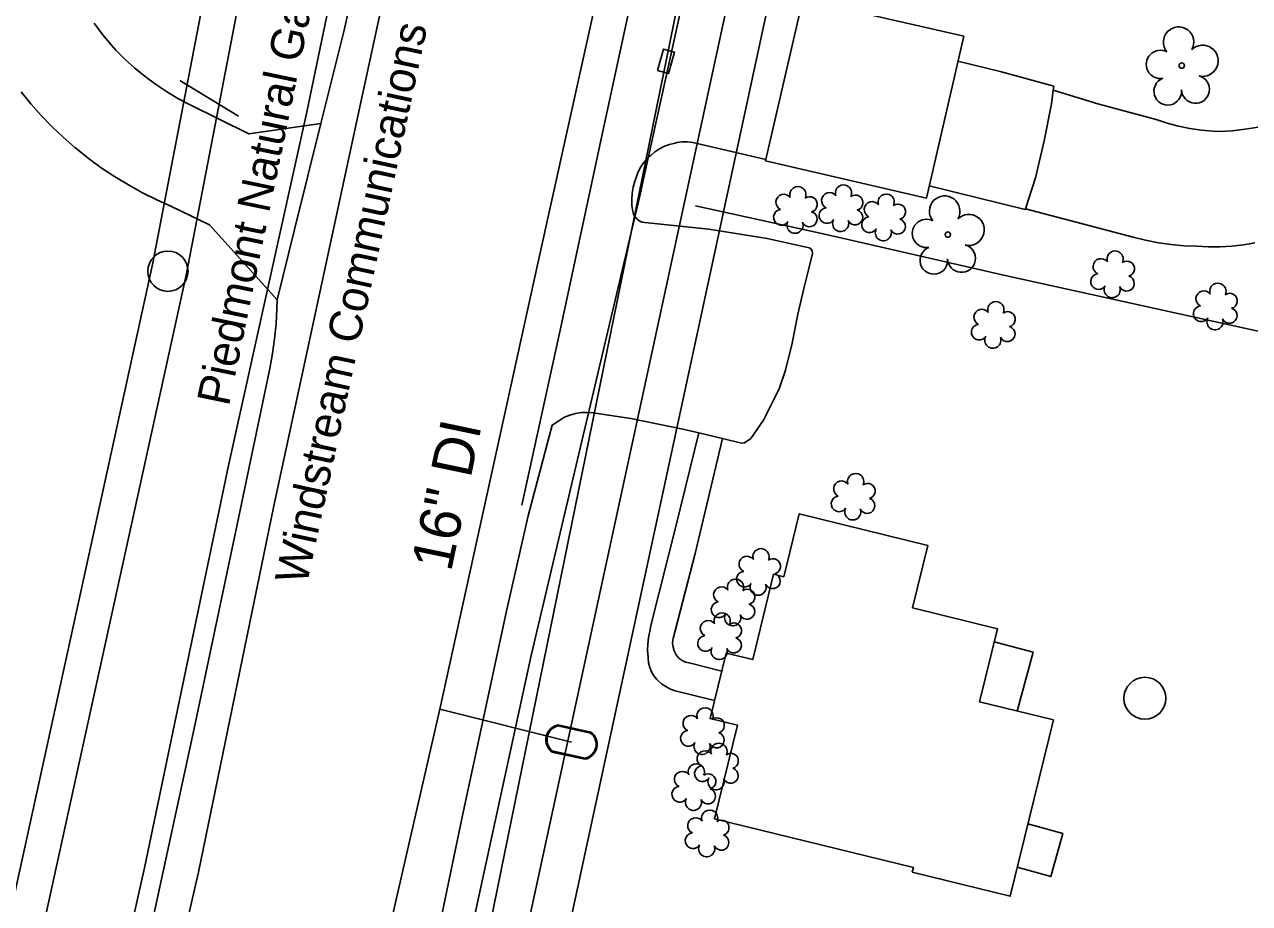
# Model space of a CAD drawing. Extents: x 1614427 to 1617186, y 896524 to 905462.
# Drawn here: x 1616442.5 to 1616592.1, y 900949.7 to 901056.9 of the extents above; entities that cross this region are included whole.
import ezdxf

# ---------------------------------------------------------------- set-up
doc = ezdxf.new("R2010")
doc.units = 0
for name, color, linetype in [('Exist Building', 7, 'Continuous'), ('Exist Building Metal Canopy', 7, 'Continuous'), ('Exist Other Culture Area Outline', 7, 'Continuous'), ('Exist Other Culture Fence Line', 7, 'Continuous'), ('Exist Other Culture Well CELL', 7, 'Continuous'), ('Exist Roads EOP', 7, 'Continuous'), ('Exist Roads EOP Other', 7, 'Continuous'), ('Exist Roads EOT', 7, 'Continuous'), ('Exist Roads Soil', 7, 'Continuous'), ('Exist Structure Minor Drop Inlet', 7, 'Continuous'), ('Exist Utilities Gas UG Line SUE LOS B', 7, 'Continuous'), ('Exist Utilities Gas UG Line SUE LOS B Text', 7, 'Continuous'), ('Exist Utilities Other Pole CELL', 7, 'Continuous'), ('Exist Utilities Power UG Cable SUE LOS D', 7, 'Continuous'), ('Exist Utilities Sanitary Sewer UG Line', 7, 'Continuous'), ('Exist Utilities Telephone UG Cable SUE LOS B', 7, 'Continuous'), ('Exist Utilities Telephone UG Cable SUE LOS B Text', 7, 'Continuous'), ('Exist Utilities Telephone UG FO SUE LOS B', 7, 'Continuous'), ('Exist Utilities Telephone UG FO SUE LOS D', 7, 'Continuous'), ('Exist Utilities TV UG FO Cable SUE LOS D', 7, 'Continuous'), ('Exist Utilities Water Meter CELL', 7, 'Continuous'), ('Exist Utilities Water UG Line SUE LOS B', 7, 'Continuous'), ('Exist Utilities Water UG Line SUE LOS B Text', 7, 'Continuous'), ('Exist Vegetation Shrub CELL', 7, 'Continuous'), ('Exist Vegetation Tree CELL', 7, 'Continuous')]:
    doc.layers.add(name, color=color, linetype=linetype)

msp = doc.modelspace()

# ---------------------------------------------------------------- linework, layer by layer
at = {"layer": 'Exist Building'}
msp.add_lwpolyline([(1616526.76, 900960), (1616529.56, 900971.41), (1616526.22, 900972.23), (1616528.18, 900980.22), (1616531.42, 900979.43), (1616533.97, 900989.83), (1616535.21, 900989.53), (1616537.09, 900997.21), (1616552.79, 900993.36), (1616550.93, 900985.74), (1616561.3, 900983.19), (1616559.11, 900974.28), (1616568.13, 900972.06), (1616562.85, 900950.53), (1616550.89, 900953.47), (1616551.04, 900954.05)], close=True, dxfattribs=at)
at = {"layer": 'Exist Building Metal Canopy'}
msp.add_lwpolyline([(1616537.54, 901060.03), (1616557.18, 901055.5), (1616552.62, 901035.75), (1616532.98, 901040.28)], close=True, dxfattribs=at)
at = {"layer": 'Exist Other Culture Area Outline'}
for points in [[(1616526.76, 900974.43), (1616521.96, 900975.59), (1616521.37, 900975.82), (1616520.81, 900976.12), (1616520.28, 900976.48), (1616519.81, 900976.91), (1616519.72, 900977), (1616519.36, 900977.45), (1616519.07, 900977.94), (1616518.85, 900978.47), (1616518.71, 900979.02), (1616518.64, 900979.59), (1616518.64, 900979.77), (1616518.59, 900980.54), (1616518.6, 900981.31), (1616518.69, 900982.08), (1616518.77, 900982.5), (1616519.03, 900983.73), (1616522.11, 900995.97), (1616524.83, 901007.08)], [(1616527.64, 900978.01), (1616523.65, 900979.01), (1616523.22, 900979.12), (1616522.81, 900979.32), (1616522.45, 900979.57), (1616522.14, 900979.89), (1616522.01, 900980.07), (1616521.81, 900980.48), (1616521.69, 900980.92), (1616521.64, 900981.37), (1616521.68, 900981.82), (1616521.71, 900982), (1616524.37, 900992.38), (1616527.71, 901006.4)], [(1616560.9, 900981.6), (1616565.64, 900980.34), (1616563.72, 900973.14)], [(1616565.02, 900959.39), (1616569.27, 900958.21), (1616567.8, 900952.94), (1616563.72, 900954.08)]]:
    msp.add_lwpolyline(points, dxfattribs=at)
at = {"layer": 'Exist Other Culture Fence Line'}
msp.add_line((1616468.64, 901045.76), (1616461.46, 901050.08), dxfattribs=at)
msp.add_lwpolyline([(1616524.45, 901034.81), (1616540.38, 901031.29), (1616562.24, 901026.28), (1616602, 901017.55)], dxfattribs=at)
at = {"layer": 'Exist Other Culture Well CELL'}
msp.add_circle((1616579.29, 900974.7), 2.56, dxfattribs=at)
at = {"layer": 'Exist Roads EOP'}
for points in [[(1616457.99, 900946.8), (1616463.22, 900971), (1616468.64, 900996.67), (1616472.45, 901014.95), (1616472.78, 901016.76), (1616473.04, 901018.57), (1616473.22, 901020.39), (1616473.33, 901022.22), (1616473.35, 901023.31), (1616475.46, 901031.92), (1616478.7, 901044.85), (1616481.54, 901056.24), (1616487.87, 901084.85), (1616490.93, 901101.42), (1616493.73, 901118.12), (1616494.93, 901124.61), (1616496.65, 901132.78), (1616498.63, 901140.3)], [(1616506.95, 901008.01), (1616504.02, 900996.97), (1616501.39, 900985.55), (1616496, 900960.38), (1616490.77, 900935.39), (1616486.24, 900914.29), (1616481.23, 900890.84), (1616476.26, 900867), (1616470.04, 900838.9), (1616463.48, 900807.17), (1616456.7, 900775.38), (1616450.29, 900746.19), (1616449.34, 900741.63)]]:
    msp.add_lwpolyline(points, dxfattribs=at)
at = {"layer": 'Exist Roads EOP Other'}
for points in [[(1616478.7, 901044.85), (1616469.88, 901043.58), (1616462.64, 901047.16), (1616461.23, 901047.91), (1616459.85, 901048.74), (1616458.52, 901049.63), (1616457.23, 901050.58), (1616455.99, 901051.6), (1616454.8, 901052.67), (1616453.66, 901053.81), (1616453.13, 901054.39), (1616452.05, 901055.71), (1616451.03, 901057.08)], [(1616556.47, 901052.46), (1616561.61, 901051.19), (1616568.16, 901049.41), (1616568.11, 901048.91), (1616567.91, 901047.25), (1616567, 901042.72), (1616565.94, 901038.21), (1616564.72, 901034.45), (1616564.68, 901034.35), (1616552.96, 901037.22)], [(1616473.35, 901023.31), (1616465.08, 901032.48), (1616460.44, 901034.71), (1616458.65, 901035.52), (1616456.9, 901036.4), (1616455.19, 901037.35), (1616453.51, 901038.37), (1616451.88, 901039.45), (1616450.3, 901040.61), (1616448.76, 901041.82), (1616448.64, 901041.92), (1616447.22, 901043.17), (1616445.85, 901044.47), (1616444.54, 901045.83), (1616443.29, 901047.25), (1616442.1, 901048.71)], [(1616506.95, 901008.01), (1616508.43, 901009), (1616509.1, 901009.26), (1616509.79, 901009.45), (1616510.5, 901009.56), (1616511.22, 901009.59), (1616511.94, 901009.55), (1616512.18, 901009.51), (1616516.54, 901008.85), (1616522.88, 901007.54), (1616524.83, 901007.08), (1616527.71, 901006.4), (1616530.05, 901005.85), (1616530.4, 901005.89), (1616531.18, 901006.41), (1616532.72, 901008.66), (1616534.66, 901012.45), (1616535.42, 901014.74), (1616536.23, 901018.05), (1616536.94, 901021.58), (1616537.7, 901024.89), (1616538.3, 901027.33), (1616538.71, 901029), (1616538.67, 901029.31), (1616538.48, 901029.58), (1616538.29, 901029.67), (1616533.17, 901030.8), (1616526.06, 901031.97), (1616518.23, 901032.75), (1616517.88, 901032.82), (1616517.55, 901032.98), (1616517.27, 901033.2), (1616517.03, 901033.48), (1616516.86, 901033.8), (1616516.78, 901034.09), (1616516.67, 901034.83), (1616516.64, 901035.59), (1616516.69, 901036.34), (1616516.81, 901037.08), (1616517.02, 901037.8), (1616517.15, 901038.14), (1616517.35, 901038.76), (1616517.63, 901039.35), (1616517.97, 901039.9), (1616518.39, 901040.4), (1616518.86, 901040.85), (1616518.96, 901040.94), (1616519.48, 901041.38), (1616520.03, 901041.76), (1616520.64, 901042.07), (1616521.27, 901042.3), (1616521.93, 901042.46), (1616522.17, 901042.51), (1616522.82, 901042.59), (1616523.47, 901042.6), (1616524.12, 901042.52), (1616524.65, 901042.4), (1616533.02, 901040.47)]]:
    msp.add_lwpolyline(points, dxfattribs=at)
at = {"layer": 'Exist Roads EOT'}
msp.add_lwpolyline([(1616503.24, 900998.28), (1616507.89, 901019.64), (1616512.97, 901043.12), (1616518.77, 901070.05)], dxfattribs=at)
at = {"layer": 'Exist Roads Soil'}
for points in [[(1616568.11, 901048.91), (1616573.54, 901047.25), (1616580.66, 901045.32), (1616582.01, 901044.89), (1616583.39, 901044.53), (1616584.78, 901044.24), (1616586.19, 901044.04), (1616587.61, 901043.91), (1616588.34, 901043.88), (1616589.94, 901043.97), (1616591.53, 901044.14), (1616593.12, 901044.4)], [(1616592.72, 901030.28), (1616591.32, 901030.04), (1616589.91, 901029.88), (1616588.49, 901029.79), (1616587.07, 901029.79), (1616585.67, 901029.86), (1616584.09, 901029.92), (1616582.51, 901030.06), (1616580.95, 901030.29), (1616579.39, 901030.59), (1616577.85, 901030.97), (1616564.72, 901034.45)]]:
    msp.add_lwpolyline(points, dxfattribs=at)
at = {"layer": 'Exist Structure Minor Drop Inlet'}
msp.add_lwpolyline([(1616519.8, 901051.31), (1616520.52, 901053.92), (1616521.85, 901053.55), (1616521.13, 901050.94)], close=True, dxfattribs=at)
at = {"layer": 'Exist Utilities Gas UG Line SUE LOS B'}
msp.add_lwpolyline([(1616533.94, 901312.88), (1616530.75, 901298.82), (1616520.32, 901250.36), (1616511.78, 901206.52), (1616502.64, 901165.78), (1616495.45, 901133.17), (1616487.34, 901096.12), (1616476.93, 901046.05), (1616467.42, 901003.11), (1616457.16, 900954), (1616446.5, 900906.58)], dxfattribs=at)
at = {"layer": 'Exist Utilities Other Pole CELL'}
msp.add_circle((1616460.02, 901026.82), 2.46, dxfattribs=at)
at = {"layer": 'Exist Utilities Power UG Cable SUE LOS D'}
msp.add_lwpolyline([(1616472.94, 900803.7), (1616497.54, 900917.27), (1616543.86, 901131.07), (1616567.27, 901236.77), (1616608.79, 901427.38), (1616667.35, 901702.61)], dxfattribs=at)
at = {"layer": 'Exist Utilities Sanitary Sewer UG Line'}
msp.add_lwpolyline([(1616444.8, 900682.93), (1616490.78, 900905.02), (1616557.11, 901230.35), (1616512.18, 901240.77), (1616568.35, 901492.88)], dxfattribs=at)
at = {"layer": 'Exist Utilities Telephone UG Cable SUE LOS B'}
msp.add_lwpolyline([(1616503.04, 901208.05), (1616504.34, 901207.7), (1616513.47, 901204.29), (1616516.02, 901201.09), (1616509.49, 901166.04), (1616502.86, 901137.25), (1616493.6, 901093.66), (1616483.21, 901045.76), (1616472.94, 900998.19), (1616463.74, 900953.48), (1616452.75, 900905.89), (1616441.22, 900852.26), (1616431.02, 900805.67), (1616418.45, 900757.41), (1616403.67, 900741.28), (1616397.61, 900729.94), (1616386.99, 900684.21), (1616386.12, 900682.91)], dxfattribs=at)
at = {"layer": 'Exist Utilities Telephone UG FO SUE LOS B'}
msp.add_lwpolyline([(1616573.32, 901304.19), (1616571.87, 901297.63), (1616562.34, 901250.69), (1616562.09, 901228.25), (1616558.13, 901219.09), (1616545.13, 901168.85), (1616535.79, 901125.09), (1616527.27, 901079.83), (1616517.65, 901036.02), (1616504.35, 900979.92), (1616494.25, 900933.3)], dxfattribs=at)
at = {"layer": 'Exist Utilities Telephone UG FO SUE LOS D'}
msp.add_lwpolyline([(1616266.21, 900145.33), (1616308.81, 900340.55), (1616349.93, 900531.55), (1616382.65, 900683.55), (1616415.98, 900835.43), (1616458.15, 901027.62), (1616484.99, 901167.15), (1616540.12, 901401.87)], dxfattribs=at)
at = {"layer": 'Exist Utilities TV UG FO Cable SUE LOS D'}
for points in [[(1616152.19, 899610.51), (1616181.4, 899742.23), (1616224.51, 899936.62), (1616270.68, 900144.79), (1616313.06, 900339.79), (1616354.51, 900530.51), (1616387.28, 900682.32), (1616420.05, 900834.14), (1616462.24, 901026.32), (1616489.27, 901166.41), (1616544.61, 901400.99), (1616575.34, 901543.24), (1616671.95, 901701.27)], [(1616351.28, 900220.72), (1616414.71, 900507.45), (1616449.63, 900671.08), (1616477.75, 900802.82), (1616502.4, 900916.25), (1616548.57, 901130.04)]]:
    msp.add_lwpolyline(points, dxfattribs=at)
at = {"layer": 'Exist Utilities Water Meter CELL'}
msp.add_line((1616509.29, 900969.36), (1616509.29, 900969.36), dxfattribs=at)
for points in [[(1616507.64, 900971.32), (1616511.62, 900970.44)], [(1616507.67, 900971.46), (1616511.65, 900970.58)], [(1616510.92, 900967.26), (1616506.91, 900968.14)], [(1616510.95, 900967.39), (1616506.94, 900968.28)]]:
    msp.add_lwpolyline(points, dxfattribs=at)
for centre, radius, start, end in [((1616508.02, 900969.63), 1.86, 100.7257, 233.5271), ((1616508.03, 900969.63), 1.73, 102.8486, 231.33), ((1616510.56, 900969.08), 1.86, 281.196, 53.8561), ((1616510.57, 900969.08), 1.73, 282.6749, 52.4205)]:
    msp.add_arc(centre, radius, start, end, dxfattribs=at)
at = {"layer": 'Exist Utilities Water UG Line SUE LOS B'}
msp.add_line((1616493.22, 900973.35), (1616509.29, 900969.36), dxfattribs=at)
msp.add_lwpolyline([(1616565.13, 901306), (1616558.38, 901275.38), (1616550.46, 901237.52), (1616546.09, 901216.65), (1616544.67, 901209.59), (1616533.76, 901160.14), (1616524.79, 901115.98), (1616518.64, 901086.8), (1616514.38, 901069.28), (1616505.14, 901027.6), (1616493.22, 900973.35), (1616487.23, 900947.29)], dxfattribs=at)
at = {"layer": 'Exist Vegetation Shrub CELL'}
for p, q in [((1616536.71, 901034.11), (1616536.71, 901034.11)), ((1616542.28, 901034.32), (1616542.28, 901034.32)), ((1616547.49, 901033.21), (1616547.49, 901033.21)), ((1616575.43, 901026.25), (1616575.43, 901026.25)), ((1616587.98, 901022.33), (1616587.98, 901022.33)), ((1616560.87, 901020.09), (1616560.87, 901020.09)), ((1616543.75, 900999.12), (1616543.75, 900999.12)), ((1616532.2, 900989.94), (1616532.2, 900989.94)), ((1616529.1, 900986.21), (1616529.1, 900986.21)), ((1616527.46, 900982.09), (1616527.46, 900982.09)), ((1616525.36, 900970.52), (1616525.36, 900970.52)), ((1616527.07, 900966.19), (1616527.07, 900966.19)), ((1616524.3, 900963.68), (1616524.3, 900963.68)), ((1616525.93, 900958.03), (1616525.93, 900958.03))]:
    msp.add_line(p, q, dxfattribs=at)
for centre, radius, start, end in [((1616536.93, 901036.15), 0.99, 334.8391, 200.4717), ((1616540.79, 901035.45), 0.968, 35.8908, 245.4216), ((1616542.5, 901036.36), 0.99, 334.8391, 200.4717), ((1616535.22, 901035.24), 0.968, 35.8908, 245.4216), ((1616538.38, 901034.98), 0.929, 284.4567, 126.0861), ((1616543.95, 901035.19), 0.929, 284.4567, 126.0861), ((1616546, 901034.34), 0.968, 35.8908, 245.4216), ((1616547.71, 901035.25), 0.99, 334.8391, 200.4717), ((1616549.16, 901034.08), 0.929, 284.4567, 126.0861), ((1616534.91, 901033.4), 0.955, 95.1099, 327.9534), ((1616538.34, 901033.18), 0.937, 204.9913, 73.4601), ((1616540.48, 901033.62), 0.955, 95.1099, 327.9534), ((1616543.91, 901033.4), 0.937, 204.9913, 73.4601), ((1616545.68, 901032.5), 0.955, 95.1099, 327.9534), ((1616536.58, 901032.43), 0.984, 151.2797, 21.387), ((1616542.15, 901032.64), 0.984, 151.2797, 21.387), ((1616547.36, 901031.52), 0.984, 151.2797, 21.387), ((1616549.12, 901032.28), 0.937, 204.9913, 73.4601), ((1616575.66, 901028.3), 0.99, 334.8391, 200.4717), ((1616573.94, 901027.38), 0.968, 35.8908, 245.4216), ((1616577.1, 901027.12), 0.929, 284.4567, 126.0861), ((1616573.63, 901025.55), 0.955, 95.1099, 327.9534), ((1616577.06, 901025.33), 0.937, 204.9913, 73.4601), ((1616575.3, 901024.57), 0.984, 151.2797, 21.387), ((1616586.5, 901023.46), 0.968, 35.8908, 245.4216), ((1616588.21, 901024.37), 0.99, 334.8391, 200.4717), ((1616561.1, 901022.13), 0.99, 334.8391, 200.4717), ((1616589.65, 901023.2), 0.929, 284.4567, 126.0861), ((1616559.39, 901021.21), 0.968, 35.8908, 245.4216), ((1616562.55, 901020.96), 0.929, 284.4567, 126.0861), ((1616586.18, 901021.63), 0.955, 95.1099, 327.9534), ((1616589.62, 901021.4), 0.937, 204.9913, 73.4601), ((1616559.07, 901019.38), 0.955, 95.1099, 327.9534), ((1616562.51, 901019.16), 0.937, 204.9913, 73.4601), ((1616587.85, 901020.65), 0.984, 151.2797, 21.387), ((1616560.74, 901018.4), 0.984, 151.2797, 21.387), ((1616543.98, 901001.16), 0.99, 334.8391, 200.4717), ((1616542.27, 901000.25), 0.968, 35.8908, 245.4216), ((1616545.43, 900999.99), 0.929, 284.4567, 126.0861), ((1616541.95, 900998.42), 0.955, 95.1099, 327.9534), ((1616545.39, 900998.19), 0.937, 204.9913, 73.4601), ((1616543.63, 900997.44), 0.984, 151.2797, 21.387), ((1616532.43, 900991.98), 0.99, 334.8391, 200.4717), ((1616530.72, 900991.06), 0.968, 35.8908, 245.4216), ((1616533.87, 900990.8), 0.929, 284.4567, 126.0861), ((1616530.4, 900989.23), 0.955, 95.1099, 327.9534), ((1616529.32, 900988.25), 0.99, 334.8391, 200.4717), ((1616532.07, 900988.25), 0.984, 151.2797, 21.387), ((1616533.84, 900989.01), 0.937, 204.9913, 73.4601), ((1616527.61, 900987.33), 0.968, 35.8908, 245.4216), ((1616530.77, 900987.08), 0.929, 284.4567, 126.0861), ((1616527.3, 900985.5), 0.955, 95.1099, 327.9534), ((1616530.73, 900985.28), 0.937, 204.9913, 73.4601), ((1616525.98, 900983.22), 0.968, 35.8908, 245.4216), ((1616527.69, 900984.13), 0.99, 334.8391, 200.4717), ((1616528.97, 900984.52), 0.984, 151.2797, 21.387), ((1616529.13, 900982.96), 0.929, 284.4567, 126.0861), ((1616525.66, 900981.39), 0.955, 95.1099, 327.9534), ((1616529.1, 900981.16), 0.937, 204.9913, 73.4601), ((1616527.33, 900980.41), 0.984, 151.2797, 21.387), ((1616525.59, 900972.56), 0.99, 334.8391, 200.4717), ((1616523.88, 900971.64), 0.968, 35.8908, 245.4216), ((1616527.03, 900971.39), 0.929, 284.4567, 126.0861), ((1616523.56, 900969.81), 0.955, 95.1099, 327.9534), ((1616525.23, 900968.83), 0.984, 151.2797, 21.387), ((1616527, 900969.59), 0.937, 204.9913, 73.4601), ((1616527.3, 900968.23), 0.99, 334.8391, 200.4717), ((1616525.59, 900967.32), 0.968, 35.8908, 245.4216), ((1616528.74, 900967.06), 0.929, 284.4567, 126.0861), ((1616524.53, 900965.72), 0.99, 334.8391, 200.4717), ((1616525.27, 900965.49), 0.955, 95.1099, 327.9534), ((1616528.71, 900965.26), 0.937, 204.9913, 73.4601), ((1616522.82, 900964.81), 0.968, 35.8908, 245.4216), ((1616525.98, 900964.55), 0.929, 284.4567, 126.0861), ((1616526.94, 900964.51), 0.984, 151.2797, 21.387), ((1616522.5, 900962.98), 0.955, 95.1099, 327.9534), ((1616525.94, 900962.75), 0.937, 204.9913, 73.4601), ((1616524.18, 900962), 0.984, 151.2797, 21.387), ((1616524.45, 900959.15), 0.968, 35.8908, 245.4216), ((1616526.16, 900960.07), 0.99, 334.8391, 200.4717), ((1616527.6, 900958.9), 0.929, 284.4567, 126.0861), ((1616524.13, 900957.32), 0.955, 95.1099, 327.9534), ((1616527.57, 900957.1), 0.937, 204.9913, 73.4601), ((1616525.8, 900956.34), 0.984, 151.2797, 21.387)]:
    msp.add_arc(centre, radius, start, end, dxfattribs=at)
at = {"layer": 'Exist Vegetation Tree CELL'}
for p, q in [((1616583.8, 901051.91), (1616583.8, 901051.91)), ((1616555.24, 901031.28), (1616555.24, 901031.28))]:
    msp.add_line(p, q, dxfattribs=at)
for centre in [(1616583.8, 901051.91), (1616555.24, 901031.28)]:
    msp.add_circle(centre, 0.326, dxfattribs=at)
for centre, radius, start, end in [((1616583.41, 901054.78), 1.86, 330.1651, 219.7134), ((1616586.35, 901052.5), 1.9, 257.1011, 134.1999), ((1616581.19, 901052.06), 1.73, 62.6636, 279.3457), ((1616582.09, 901048.79), 1.69, 111.5671, 6.231), ((1616585.47, 901049.01), 1.7, 181.2822, 74.56), ((1616554.85, 901034.15), 1.86, 330.1651, 219.7134), ((1616557.79, 901031.86), 1.9, 257.1011, 134.1999), ((1616552.63, 901031.43), 1.73, 62.6636, 279.3457), ((1616553.53, 901028.15), 1.69, 111.5671, 6.231), ((1616556.91, 901028.38), 1.7, 181.2822, 74.56)]:
    msp.add_arc(centre, radius, start, end, dxfattribs=at)

# ---------------------------------------------------------------- texts
at = {"layer": 'Exist Utilities Gas UG Line SUE LOS B Text'}
msp.add_text('Piedmont Natural Gas Company Inc.', height=4, rotation=78.2622, dxfattribs=at).set_placement((1616467.45, 901010.23))
at = {"layer": 'Exist Utilities Telephone UG Cable SUE LOS B Text'}
msp.add_text('Windstream Communications Inc.', height=4, rotation=77.8159, dxfattribs=at).set_placement((1616476.97, 900988.43))
at = {"layer": 'Exist Utilities Water UG Line SUE LOS B Text'}
msp.add_text('16" DI', height=5, rotation=78.1797, dxfattribs=at).set_placement((1616494.58, 900990.03))

doc.saveas('drawing.dxf')
